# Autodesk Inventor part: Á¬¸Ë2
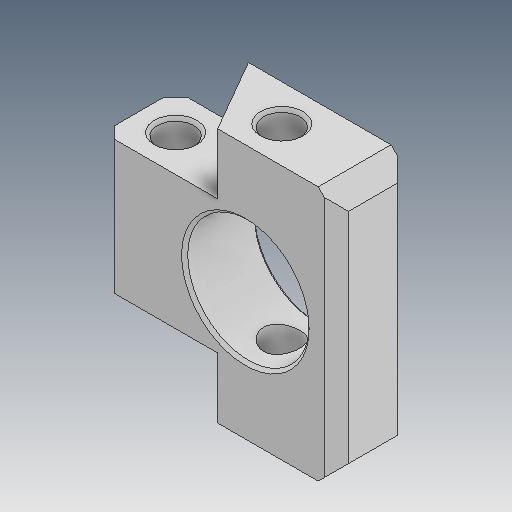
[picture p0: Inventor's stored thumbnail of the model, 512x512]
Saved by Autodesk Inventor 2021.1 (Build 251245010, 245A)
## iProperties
Created: 2013-04
Part Number: Á¬¸Ë2
Material: Ogólny
Document SubType Name: Modeling
Designer: user
Density: 1 g/cm^3
Appearance: Domyślna
Author: user
Revision Number: ÈÎºÎ
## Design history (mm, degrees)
feature "µ¹½Ç3"
node "Bryła1"
